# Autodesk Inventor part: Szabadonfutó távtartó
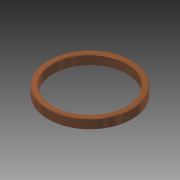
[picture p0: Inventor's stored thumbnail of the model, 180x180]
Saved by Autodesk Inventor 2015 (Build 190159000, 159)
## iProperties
Created: 2013-02
Part Number: Szabadonfutó távtartó
Material: Generic
Document SubType Name: Modeling
Designer: Marci
Density: 1 g/cm^3
Appearance: Copper - Satin
Author: Marci
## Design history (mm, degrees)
sketch "Sketch1"
  geometry: C1 r 15.25 at (0, 0); C2 r 17.5 at (0, 0); 1 further point
  constraints: 2 centre point, 2 coincident
  dimensions: "d0" = 30.5 diameter of C1; "d1" = 35 diameter of C2
extrude "Extrusion1" new body sketch "Sketch1" distance "d2" = 4; taper "d3" = 0 deg
chamfer "Chamfer1" distance "d4" = 0.25; stored, may be unused: second distance "d5" = 2, angle "d6" = 45 deg
body "Solid1"
